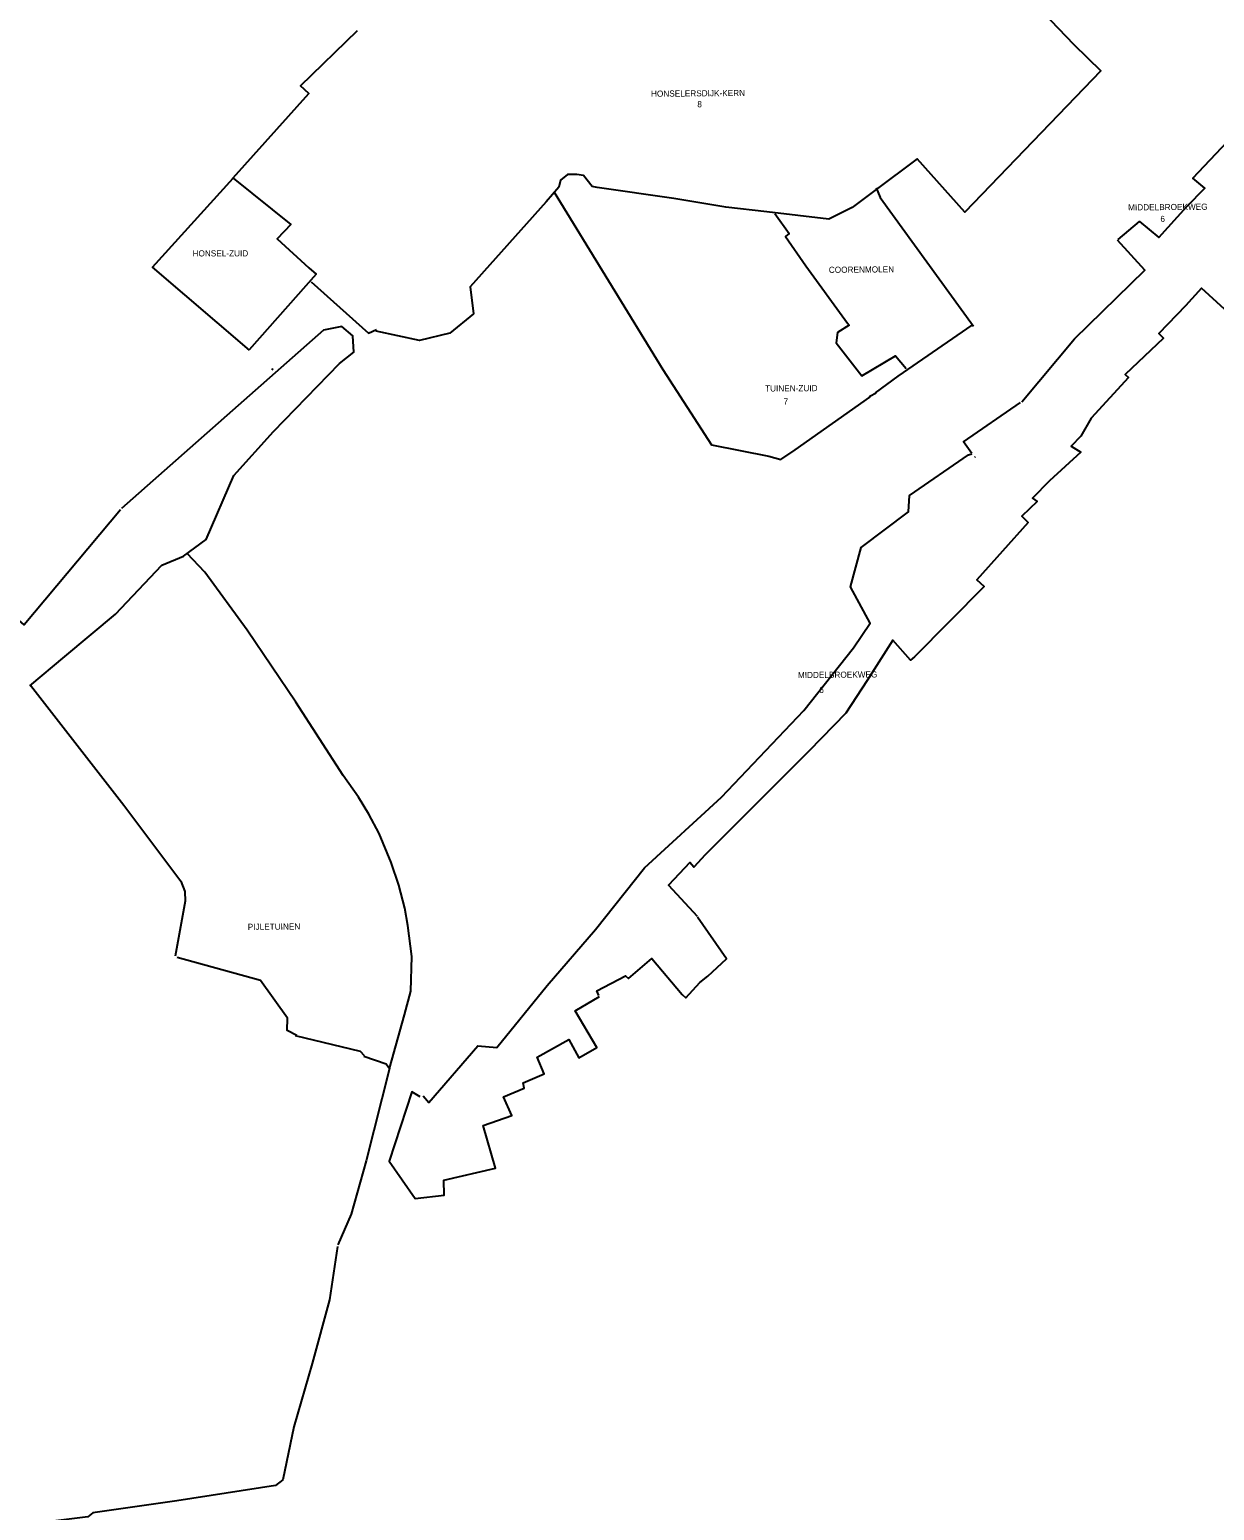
# Model space of a CAD drawing. Extents: x 69068 to 80855, y 440023 to 451362.
# Drawn here: x 74532 to 76267, y 445078 to 447248 of the extents above; entities that cross this region are included whole.
import ezdxf

# ---------------------------------------------------------------- set-up
doc = ezdxf.new("R2010")
doc.units = 0
for name, color, linetype in [('Bemalingsgebiedsgrens', 7, 'Continuous'), ('Bemalingsgebiedsnummer', 7, 'Continuous'), ('RIO_Leidingen', 7, 'Continuous')]:
    doc.layers.add(name, color=color, linetype=linetype)

msp = doc.modelspace()

# ---------------------------------------------------------------- linework, layer by layer
at = {"layer": 'Bemalingsgebiedsgrens'}
for points in [[(75947.4, 447344.9), (76061.2, 447225.9), (76101.1, 447187.3), (75901.5, 446980.2), (75831.9, 447058.3), (75769.7, 447011.7), (75736.7, 446986.8), (75702.6, 446970), (75611.9, 446980.7), (75551.7, 446987.5), (75475.5, 447000), (75363.3, 447016.3), (75356, 447017.7), (75343.3, 447033.8), (75333.5, 447035.4), (75319.7, 447035.5), (75309.4, 447027), (75307.1, 447016.7), (75288.5, 446995.5), (75177.4, 446870.6), (75182.1, 446831), (75147.5, 446802.9), (75103.2, 446792.4), (75039.6, 446805.9)], [(74830.1, 447030.4), (74941, 447154.2), (74928.7, 447165.2), (75012.4, 447246.4)], [(76126.3, 446940.1), (76157.6, 446966.7), (76185.6, 446942.9), (76226.9, 446988.3), (76253.2, 447015.2), (76235.5, 447030.2), (76286.2, 447083.7)], [(74854.2, 446778), (74712, 446899.8), (74830.1, 447030.1), (74914.9, 446962.2), (74894.5, 446941.3), (74941, 446898.4), (74951.9, 446889.3), (74853.7, 446778.6)], [(74828.6, 447031), (74830.3, 447029.6)], [(75772, 447015.6), (75777.5, 447001.8), (75914.5, 446813.2)], [(75300.6, 447009.6), (75459.4, 446749.6), (75530.8, 446639.1), (75614.6, 446622.9), (75632.5, 446618), (75653.2, 446631.8), (75762.7, 446709.3), (75762.5, 446710.5), (75771.8, 446715.3)], [(75623.7, 446978), (75644.4, 446949.1), (75639, 446944.7), (75669.1, 446901.8), (75729.8, 446817.5), (75732.2, 446814.7), (75715.4, 446803.8), (75713.5, 446788.8), (75750.7, 446740.4), (75800.4, 446769.9), (75815.7, 446751.3)], [(75985.4, 446702.3), (76062.3, 446794.6), (76165.2, 446895.3), (76125.1, 446939)], [(74943, 446879.2), (74942.5, 446878.7)], [(74944.6, 446878.2), (75028.5, 446803.1), (75040.4, 446808.3)], [(76293.4, 446827.9), (76248.2, 446868.6), (76224.9, 446842.9), (76185.6, 446802.4), (76192.8, 446795.7), (76136.3, 446742.5), (76141.2, 446737.8), (76086.9, 446678.5), (76071.4, 446652.2), (76057.3, 446637.2), (76071.7, 446628.4), (76025.7, 446586.8), (76000.8, 446561.3), (76007.7, 446556.1), (75985, 446534.7), (75994.7, 446525.6), (75919.3, 446441.6), (75924, 446436.9), (75930.1, 446431.6), (75828.1, 446328.8), (75822, 446323.6), (75796.3, 446352.9), (75758.6, 446293.9), (75727.3, 446246), (75673.8, 446191.1), (75521.7, 446038.7), (75505, 446020.7), (75499.2, 446027.4), (75467.9, 445994.4), (75509.7, 445948.9)], [(74532.3, 446286.1), (74583.6, 446329.1), (74658.1, 446391.1), (74725.9, 446463), (74757.8, 446476.3), (74790.8, 446500.8), (74831.5, 446594.3), (74889.6, 446659), (74985.8, 446758.3), (75006.8, 446775), (75005.6, 446799), (74989.4, 446812.8), (74962.5, 446807.4), (74666.9, 446545.8)], [(75911.8, 446814.5), (75803.7, 446739.8), (75770.2, 446715.6)], [(74888, 446749.7), (74887.1, 446750.5)], [(74888.9, 446749), (74888, 446749.7)], [(75911.8, 446626.4), (75899.6, 446643.9), (75983, 446701.5)], [(75108.6, 445685.4), (75117, 445676), (75188.4, 445758.6), (75216.2, 445756.4), (75289.9, 445847.2), (75360.8, 445929.3), (75432.8, 446019.7), (75545.3, 446123.2), (75666.2, 446250.1), (75738.8, 446342.1), (75763.1, 446378.2), (75734.3, 446431.4), (75749.8, 446489), (75819.1, 446541.1), (75820.8, 446564.9), (75907.2, 446624.8), (75912.1, 446625.9)], [(75916.4, 446621.3), (75917.3, 446622.1)], [(74665.4, 446544), (74524.1, 446375.8), (74402.6, 446481.8), (74360.6, 446435.1), (74224.9, 446551.9)], [(75059.4, 445725.7), (75081.2, 445804), (75090.3, 445839.1), (75092, 445889.5), (75086.3, 445935.3), (75081.8, 445960.7), (75073, 445994.2), (75061.5, 446027.2), (75044.1, 446069.7), (75028.8, 446098.2), (75013.9, 446123.3), (74991.6, 446155), (74922, 446262.5), (74850.7, 446367.9), (74788.8, 446452.9), (74763, 446480.1)], [(74533.4, 446287), (74670, 446111.5), (74753.8, 446000.2), (74759.3, 445984.8), (74759.8, 445970.8), (74745.3, 445890.3)], [(75365.9, 445832.3), (75362.6, 445839.2), (75405, 445861.4), (75409.4, 445857.5), (75443.5, 445886.9), (75487.8, 445834.2), (75493.4, 445829), (75513.6, 445851.4), (75525.3, 445860.8), (75552.7, 445886.3), (75510.3, 445947.5)], [(74923.5, 445773.8), (74909.6, 445781.5), (74910, 445799.2), (74870.4, 445854.6), (74748.4, 445888.4)], [(75104.1, 445684.2), (75091.9, 445691.4), (75058.6, 445590), (75096.6, 445535.2), (75139.3, 445539.9), (75138.7, 445562.1), (75214.6, 445579.6), (75196.6, 445641.9), (75238.5, 445656.9), (75226.3, 445684.3), (75256.5, 445696.8), (75254.8, 445704.5), (75285.8, 445717.6), (75275.3, 445742.2), (75321.9, 445768.3), (75336.3, 445741.4), (75362.9, 445756.6), (75331.3, 445810.1), (75366.5, 445831.2)], [(75022.4, 445744.2), (75016.6, 445750.4), (74921.8, 445773.4)], [(75021.6, 445743.6), (75054.5, 445732.5), (75059.4, 445725.7), (75025, 445590.1), (75003, 445512.3), (74983.5, 445467.1)], [(74983.2, 445464.7), (74971.2, 445386.7), (74946, 445293.2), (74919, 445200.4), (74903.1, 445122.8), (74892.4, 445114.5), (74748, 445092.1), (74625, 445074.4), (74617.6, 445068.6), (74488.9, 445052.8), (74342.2, 445035.1), (74344.9, 445009.3), (74265.7, 444998), (74189.4, 444991.5), (74052.4, 444980.2), (73995.3, 444976.9), (73997, 444947.7)]]:
    msp.add_lwpolyline(points, dxfattribs=at)

# ---------------------------------------------------------------- texts
at = {"layer": 'Bemalingsgebiedsnummer'}
for s, p in [('8', (75510, 447133.9)), ('6', (76188.1, 446965.8)), ('7', (75636.2, 446698.3)), ('6', (75688.6, 446275.7))]:
    msp.add_text(s, height=9, rotation=0.1635, dxfattribs=at).set_placement(p)
at = {"layer": 'RIO_Leidingen'}
for s, rotation, p in [('HONSELERSDIJK-KERN', 0.5, (75442.2, 447149.2)), ('MIDDELBROEKWEG', 0.5, (76140.9, 446982.7)), ('HONSEL-ZUID', 0.0707, (74770.8, 446915.3)), ('COORENMOLEN', 0.5, (75702.6, 446891.2)), ('TUINEN-ZUID', 0.5, (75609.2, 446717.3)), ('MIDDELBROEKWEG', 0.5, (75657.3, 446297.5)), ('PIJLETUINEN', 0.5, (74851.7, 445928.6))]:
    msp.add_text(s, height=9, rotation=rotation, dxfattribs=at).set_placement(p)

doc.saveas('drawing.dxf')
